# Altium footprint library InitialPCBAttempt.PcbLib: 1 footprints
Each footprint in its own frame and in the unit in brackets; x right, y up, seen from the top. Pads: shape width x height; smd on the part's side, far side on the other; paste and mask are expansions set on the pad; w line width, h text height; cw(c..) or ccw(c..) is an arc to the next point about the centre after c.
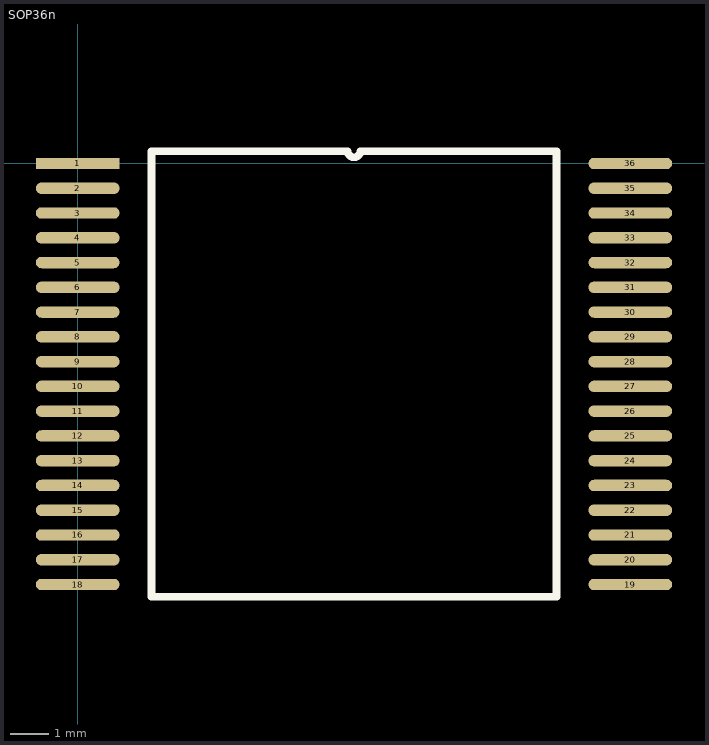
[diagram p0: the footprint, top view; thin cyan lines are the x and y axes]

## SOP36n [mm]
pads (36):
  rect 2.2x0.3 smd: 1(0,0)
  oval 2.2x0.3 smd: 2(0,-0.65) 3(0,-1.3) 4(0,-1.95) 5(0,-2.6) 6(0,-3.25) 7(0,-3.9) 8(0,-4.55) 9(0,-5.2) 10(0,-5.85) 11(0,-6.5) 12(0,-7.15) 13(0,-7.8) 14(0,-8.45) 15(0,-9.1) 16(0,-9.75) 17(0,-10.4) 18(0,-11.05) 19(14.5,-11.05) 20(14.5,-10.4) 21(14.5,-9.75) 22(14.5,-9.1) 23(14.5,-8.45) 24(14.5,-7.8) 25(14.5,-7.15) 26(14.5,-6.5) 27(14.5,-5.85) 28(14.5,-5.2) 29(14.5,-4.55) 30(14.5,-3.9) 31(14.5,-3.25) 32(14.5,-2.6) 33(14.5,-1.95) 34(14.5,-1.3) 35(14.5,-0.65) 36(14.5,0)
Top Overlay:
  lines w0.2: 1.935,-11.375 12.565,-11.375 12.565,0.325 7.412,0.325 cw(c7.25,0.325) 7.087,0.325 1.935,0.325 1.935,-11.375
